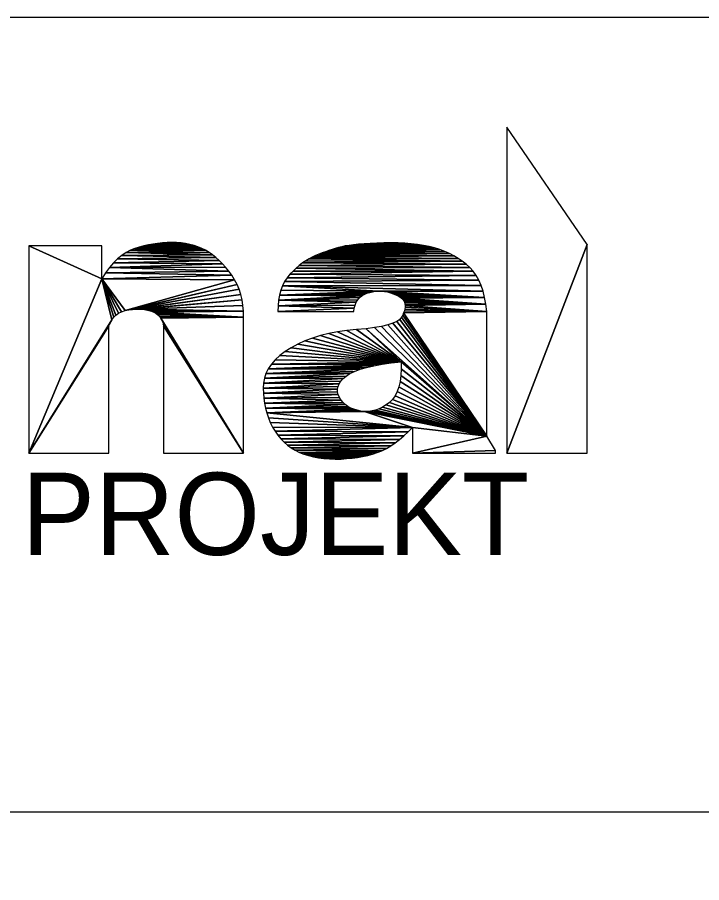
# Model space of a CAD drawing. Extents: x -1210 to -790, y -790 to -493.
# Drawn here: x -950.3 to -931.18, y -751.97 to -727.77 of the extents above; entities that cross this region are included whole.
import ezdxf

# ---------------------------------------------------------------- set-up
doc = ezdxf.new("R2010")
doc.units = 0
doc.layers.add('Vrstva 1', color=7, linetype='Continuous')

msp = doc.modelspace()

# ---------------------------------------------------------------- linework, layer by layer
at = {"layer": 'Vrstva 1'}
msp.add_line((-855, -750), (-970, -750), dxfattribs=at)
for points in [[(-970, -727.774), (-805, -727.774), (-805, -780), (-970, -780)], [(-936.62, -730.842), (-936.62, -739.962), (-934.38, -734.122)], [(-946.509, -734.114), (-946.638, -734.136), (-945.478, -734.124)], [(-946.379, -734.096), (-946.509, -734.114), (-945.597, -734.1)], [(-945.597, -734.1), (-946.509, -734.114), (-945.478, -734.124)], [(-946.247, -734.082), (-946.379, -734.096), (-945.721, -734.084)], [(-945.721, -734.084), (-946.379, -734.096), (-945.597, -734.1)], [(-946.115, -734.074), (-946.247, -734.082), (-945.721, -734.084)], [(-945.981, -734.072), (-946.115, -734.074), (-945.849, -734.074)], [(-945.849, -734.074), (-946.115, -734.074), (-945.721, -734.084)], [(-940.611, -734.104), (-940.766, -734.118), (-939.293, -734.106)], [(-939.293, -734.106), (-940.766, -734.118), (-939.119, -734.126)], [(-940.442, -734.094), (-940.611, -734.104), (-939.293, -734.106)], [(-940.258, -734.086), (-940.442, -734.094), (-939.474, -734.09)], [(-939.474, -734.09), (-940.442, -734.094), (-939.293, -734.106)], [(-940.059, -734.08), (-940.258, -734.086), (-939.661, -734.082)], [(-939.661, -734.082), (-940.258, -734.086), (-939.474, -734.09)], [(-939.857, -734.078), (-940.059, -734.08), (-939.661, -734.082)], [(-947.94, -735.082), (-947.94, -734.162), (-949.98, -734.162)], [(-949.98, -734.162), (-949.98, -739.962), (-947.94, -735.082)], [(-947.263, -734.348), (-947.382, -734.43), (-944.847, -734.414)], [(-947.142, -734.284), (-947.263, -734.348), (-945.044, -734.288)], [(-945.044, -734.288), (-947.263, -734.348), (-944.944, -734.346)], [(-944.944, -734.346), (-947.263, -734.348), (-944.847, -734.414)], [(-945.146, -734.236), (-947.142, -734.284), (-945.044, -734.288)], [(-947.018, -734.236), (-947.142, -734.284), (-945.146, -734.236)], [(-946.892, -734.198), (-947.018, -734.236), (-945.146, -734.236)], [(-946.766, -734.164), (-946.892, -734.198), (-945.252, -734.192)], [(-945.252, -734.192), (-946.892, -734.198), (-945.146, -734.236)], [(-946.638, -734.136), (-946.766, -734.164), (-945.363, -734.154)], [(-945.363, -734.154), (-946.766, -734.164), (-945.252, -734.192)], [(-945.478, -734.124), (-946.638, -734.136), (-945.363, -734.154)], [(-941.687, -734.328), (-941.779, -734.362), (-938.226, -734.376)], [(-941.595, -734.298), (-941.687, -734.328), (-938.358, -734.318)], [(-938.358, -734.318), (-941.687, -734.328), (-938.226, -734.376)], [(-941.505, -734.268), (-941.595, -734.298), (-938.358, -734.318)], [(-941.415, -734.24), (-941.505, -734.268), (-938.497, -734.266)], [(-938.497, -734.266), (-941.505, -734.268), (-938.358, -734.318)], [(-941.325, -734.214), (-941.415, -734.24), (-938.642, -734.222)], [(-938.642, -734.222), (-941.415, -734.24), (-938.497, -734.266)], [(-941.237, -734.19), (-941.325, -734.214), (-938.642, -734.222)], [(-941.141, -734.168), (-941.237, -734.19), (-938.794, -734.184)], [(-938.794, -734.184), (-941.237, -734.19), (-938.642, -734.222)], [(-941.03, -734.15), (-941.141, -734.168), (-938.953, -734.152)], [(-938.953, -734.152), (-941.141, -734.168), (-938.794, -734.184)], [(-940.905, -734.132), (-941.03, -734.15), (-938.953, -734.152)], [(-940.766, -734.118), (-940.905, -734.132), (-939.119, -734.126)], [(-939.119, -734.126), (-940.905, -734.132), (-938.953, -734.152)], [(-934.38, -734.122), (-936.62, -739.962), (-934.38, -739.962)], [(-947.498, -734.528), (-947.612, -734.642), (-944.659, -734.572)], [(-944.659, -734.572), (-947.612, -734.642), (-944.568, -734.664)], [(-947.382, -734.43), (-947.498, -734.528), (-944.752, -734.488)], [(-944.752, -734.488), (-947.498, -734.528), (-944.659, -734.572)], [(-944.847, -734.414), (-947.382, -734.43), (-944.752, -734.488)], [(-942.242, -734.58), (-942.332, -734.642), (-937.866, -734.592)], [(-937.866, -734.592), (-942.332, -734.642), (-937.759, -734.678)], [(-942.15, -734.524), (-942.242, -734.58), (-937.866, -734.592)], [(-942.058, -734.476), (-942.15, -734.524), (-937.98, -734.514)], [(-937.98, -734.514), (-942.15, -734.524), (-937.866, -734.592)], [(-941.965, -734.434), (-942.058, -734.476), (-938.1, -734.442)], [(-938.1, -734.442), (-942.058, -734.476), (-937.98, -734.514)], [(-941.871, -734.398), (-941.965, -734.434), (-938.1, -734.442)], [(-941.779, -734.362), (-941.871, -734.398), (-938.226, -734.376)], [(-938.226, -734.376), (-941.871, -734.398), (-938.1, -734.442)], [(-947.724, -734.772), (-947.833, -734.918), (-944.393, -734.872)], [(-947.612, -734.642), (-947.724, -734.772), (-944.568, -734.664)], [(-944.568, -734.664), (-947.724, -734.772), (-944.479, -734.764)], [(-944.479, -734.764), (-947.724, -734.772), (-944.393, -734.872)], [(-942.509, -734.788), (-942.596, -734.87), (-937.565, -734.874)], [(-942.421, -734.712), (-942.509, -734.788), (-937.658, -734.77)], [(-937.658, -734.77), (-942.509, -734.788), (-937.565, -734.874)], [(-942.332, -734.642), (-942.421, -734.712), (-937.759, -734.678)], [(-937.759, -734.678), (-942.421, -734.712), (-937.658, -734.77)], [(-947.94, -735.082), (-949.98, -739.962), (-947.662, -736.23)], [(-947.833, -734.918), (-947.94, -735.082), (-944.308, -734.988)], [(-944.308, -734.988), (-947.94, -735.082), (-944.229, -735.112)], [(-947.94, -735.082), (-947.291, -735.976), (-944.229, -735.112)], [(-947.94, -735.082), (-947.385, -736.006), (-947.291, -735.976)], [(-947.94, -735.082), (-947.469, -736.048), (-947.385, -736.006)], [(-947.94, -735.082), (-947.543, -736.098), (-947.469, -736.048)], [(-947.94, -735.082), (-947.607, -736.16), (-947.543, -736.098)], [(-947.94, -735.082), (-947.662, -736.23), (-947.607, -736.16)], [(-944.393, -734.872), (-947.833, -734.918), (-944.308, -734.988)], [(-942.763, -735.058), (-942.832, -735.164), (-937.407, -735.124)], [(-942.682, -734.96), (-942.763, -735.058), (-937.481, -734.992)], [(-937.481, -734.992), (-942.763, -735.058), (-937.407, -735.124)], [(-942.596, -734.87), (-942.682, -734.96), (-937.565, -734.874)], [(-937.565, -734.874), (-942.682, -734.96), (-937.481, -734.992)], [(-944.229, -735.112), (-947.291, -735.976), (-944.161, -735.242)], [(-944.161, -735.242), (-947.291, -735.976), (-947.187, -735.954)], [(-944.161, -735.242), (-947.187, -735.954), (-944.104, -735.378)], [(-942.89, -735.28), (-942.938, -735.406), (-940.209, -735.43)], [(-942.832, -735.164), (-942.89, -735.28), (-937.343, -735.27)], [(-937.343, -735.27), (-942.89, -735.28), (-937.288, -735.432)], [(-942.89, -735.28), (-940.209, -735.43), (-937.288, -735.432)], [(-937.407, -735.124), (-942.832, -735.164), (-937.343, -735.27)], [(-944.104, -735.378), (-947.187, -735.954), (-944.058, -735.522)], [(-944.058, -735.522), (-947.187, -735.954), (-947.081, -735.942)], [(-944.058, -735.522), (-947.081, -735.942), (-944.022, -735.672)], [(-942.975, -735.54), (-943.001, -735.686), (-940.678, -735.562)], [(-940.678, -735.562), (-943.001, -735.686), (-940.737, -735.612)], [(-942.938, -735.406), (-942.975, -735.54), (-940.209, -735.43)], [(-940.209, -735.43), (-942.975, -735.54), (-940.291, -735.434)], [(-940.291, -735.434), (-942.975, -735.54), (-940.373, -735.446)], [(-940.373, -735.446), (-942.975, -735.54), (-940.454, -735.464)], [(-940.454, -735.464), (-942.975, -735.54), (-940.535, -735.488)], [(-940.535, -735.488), (-942.975, -735.54), (-940.611, -735.52)], [(-940.611, -735.52), (-942.975, -735.54), (-940.678, -735.562)], [(-940.209, -735.43), (-940.127, -735.432), (-937.288, -735.432)], [(-940.127, -735.432), (-940.044, -735.44), (-937.288, -735.432)], [(-937.288, -735.432), (-940.044, -735.44), (-937.243, -735.608)], [(-940.044, -735.44), (-939.96, -735.454), (-937.243, -735.608)], [(-939.96, -735.454), (-939.876, -735.476), (-937.243, -735.608)], [(-939.876, -735.476), (-939.796, -735.502), (-937.243, -735.608)], [(-939.796, -735.502), (-939.724, -735.53), (-937.243, -735.608)], [(-939.724, -735.53), (-939.662, -735.56), (-937.243, -735.608)], [(-939.662, -735.56), (-939.608, -735.592), (-937.243, -735.608)], [(-944.022, -735.672), (-947.081, -735.942), (-946.98, -735.934)], [(-944.022, -735.672), (-946.98, -735.934), (-946.885, -735.934)], [(-944.022, -735.672), (-946.885, -735.934), (-943.998, -735.83)], [(-943.001, -735.686), (-943.016, -735.84), (-940.828, -735.74)], [(-940.828, -735.74), (-943.016, -735.84), (-940.861, -735.818)], [(-940.737, -735.612), (-943.001, -735.686), (-940.787, -735.672)], [(-940.787, -735.672), (-943.001, -735.686), (-940.828, -735.74)], [(-939.608, -735.592), (-939.563, -735.626), (-937.243, -735.608)], [(-937.243, -735.608), (-939.563, -735.626), (-937.207, -735.798)], [(-939.563, -735.626), (-939.526, -735.662), (-937.207, -735.798)], [(-939.526, -735.662), (-939.499, -735.7), (-937.207, -735.798)], [(-939.499, -735.7), (-939.48, -735.74), (-937.207, -735.798)], [(-939.48, -735.74), (-939.468, -735.784), (-937.207, -735.798)], [(-939.468, -735.784), (-939.463, -735.83), (-937.207, -735.798)], [(-937.207, -735.798), (-939.463, -735.83), (-937.18, -736.002)], [(-943.998, -735.83), (-946.885, -735.934), (-943.984, -735.992)], [(-946.885, -735.934), (-946.794, -735.938), (-943.984, -735.992)], [(-946.794, -735.938), (-946.709, -735.95), (-943.984, -735.992)], [(-946.709, -735.95), (-946.63, -735.968), (-943.984, -735.992)], [(-946.63, -735.968), (-946.555, -735.992), (-943.984, -735.992)], [(-946.555, -735.992), (-946.486, -736.022), (-943.984, -735.992)], [(-943.984, -735.992), (-946.486, -736.022), (-943.98, -736.162)], [(-946.486, -736.022), (-946.424, -736.056), (-943.98, -736.162)], [(-943.016, -735.84), (-943.02, -736.002), (-940.885, -735.906)], [(-940.885, -735.906), (-943.02, -736.002), (-940.9, -736.002)], [(-940.861, -735.818), (-943.016, -735.84), (-940.885, -735.906)], [(-939.506, -736.04), (-939.532, -736.1), (-937.18, -739.482)], [(-939.486, -735.984), (-939.506, -736.04), (-937.18, -736.002)], [(-937.18, -736.002), (-939.506, -736.04), (-937.18, -739.482)], [(-939.472, -735.93), (-939.486, -735.984), (-937.18, -736.002)], [(-939.464, -735.878), (-939.472, -735.93), (-937.18, -736.002)], [(-939.463, -735.83), (-939.464, -735.878), (-937.18, -736.002)], [(-947.662, -736.23), (-949.98, -739.962), (-947.706, -736.312)], [(-946.424, -736.056), (-946.37, -736.094), (-943.98, -736.162)], [(-946.37, -736.094), (-946.324, -736.136), (-943.98, -736.162)], [(-946.324, -736.136), (-946.287, -736.182), (-943.98, -736.162)], [(-943.98, -736.162), (-946.287, -736.182), (-943.98, -739.962)], [(-946.287, -736.182), (-946.258, -736.232), (-943.98, -739.962)], [(-946.258, -736.232), (-946.237, -736.284), (-943.98, -739.962)], [(-946.237, -736.284), (-946.225, -736.342), (-943.98, -739.962)], [(-939.696, -736.28), (-939.807, -736.33), (-937.18, -739.482)], [(-939.615, -736.224), (-939.696, -736.28), (-937.18, -739.482)], [(-939.564, -736.162), (-939.615, -736.224), (-937.18, -739.482)], [(-939.532, -736.1), (-939.564, -736.162), (-937.18, -739.482)], [(-947.706, -736.312), (-949.98, -739.962), (-947.74, -736.402)], [(-947.74, -736.402), (-949.98, -739.962), (-947.74, -739.962)], [(-946.225, -736.342), (-946.22, -736.402), (-943.98, -739.962)], [(-946.22, -736.402), (-946.22, -739.962), (-943.98, -739.962)], [(-941.091, -736.532), (-941.35, -736.568), (-939.576, -737.406)], [(-940.819, -736.504), (-941.091, -736.532), (-939.576, -737.406)], [(-940.556, -736.48), (-940.819, -736.504), (-939.576, -737.406)], [(-940.323, -736.45), (-940.556, -736.48), (-937.18, -739.482)], [(-940.556, -736.48), (-939.576, -737.406), (-937.18, -739.482)], [(-940.121, -736.416), (-940.323, -736.45), (-937.18, -739.482)], [(-939.949, -736.376), (-940.121, -736.416), (-937.18, -739.482)], [(-939.807, -736.33), (-939.949, -736.376), (-937.18, -739.482)], [(-942.055, -736.744), (-942.266, -736.824), (-939.576, -737.406)], [(-941.833, -736.674), (-942.055, -736.744), (-939.576, -737.406)], [(-941.598, -736.616), (-941.833, -736.674), (-939.576, -737.406)], [(-941.35, -736.568), (-941.598, -736.616), (-939.576, -737.406)], [(-942.65, -737.014), (-942.819, -737.122), (-939.576, -737.406)], [(-942.464, -736.914), (-942.65, -737.014), (-939.576, -737.406)], [(-942.266, -736.824), (-942.464, -736.914), (-939.576, -737.406)], [(-942.967, -737.234), (-943.095, -737.352), (-939.576, -737.406)], [(-942.819, -737.122), (-942.967, -737.234), (-939.576, -737.406)], [(-940.11, -737.474), (-943.287, -737.6), (-940.339, -737.516)], [(-943.201, -737.474), (-943.287, -737.6), (-940.11, -737.474)], [(-943.095, -737.352), (-943.201, -737.474), (-939.576, -737.406)], [(-939.576, -737.406), (-943.201, -737.474), (-939.855, -737.438)], [(-939.855, -737.438), (-943.201, -737.474), (-940.11, -737.474)], [(-939.576, -737.406), (-939.571, -737.606), (-937.18, -739.482)], [(-943.352, -737.73), (-943.396, -737.866), (-941.005, -737.736)], [(-941.005, -737.736), (-943.396, -737.866), (-941.108, -737.804)], [(-943.287, -737.6), (-943.352, -737.73), (-940.723, -737.616)], [(-940.723, -737.616), (-943.352, -737.73), (-940.876, -737.674)], [(-940.876, -737.674), (-943.352, -737.73), (-941.005, -737.736)], [(-940.339, -737.516), (-943.287, -737.6), (-940.544, -737.564)], [(-940.544, -737.564), (-943.287, -737.6), (-940.723, -737.616)], [(-939.571, -737.606), (-939.58, -737.788), (-937.18, -739.482)], [(-943.396, -737.866), (-943.419, -738.006), (-941.191, -737.876)], [(-941.191, -737.876), (-943.419, -738.006), (-941.257, -737.948)], [(-941.257, -737.948), (-943.419, -738.006), (-941.306, -738.022)], [(-941.108, -737.804), (-943.396, -737.866), (-941.191, -737.876)], [(-939.602, -737.954), (-939.636, -738.102), (-937.18, -739.482)], [(-939.58, -737.788), (-939.602, -737.954), (-937.18, -739.482)], [(-943.419, -738.006), (-943.427, -738.146), (-941.306, -738.022)], [(-941.306, -738.022), (-943.427, -738.146), (-941.338, -738.096)], [(-941.338, -738.096), (-943.427, -738.146), (-941.354, -738.172)], [(-943.427, -738.146), (-943.426, -738.286), (-941.354, -738.172)], [(-941.354, -738.172), (-943.426, -738.286), (-941.353, -738.248)], [(-939.636, -738.102), (-939.684, -738.236), (-937.18, -739.482)], [(-941.353, -738.248), (-943.426, -738.286), (-941.335, -738.324)], [(-943.426, -738.286), (-943.416, -738.426), (-941.335, -738.324)], [(-941.335, -738.324), (-943.416, -738.426), (-941.301, -738.402)], [(-941.301, -738.402), (-943.416, -738.426), (-941.254, -738.476)], [(-943.416, -738.426), (-943.397, -738.564), (-941.254, -738.476)], [(-939.818, -738.456), (-939.904, -738.54), (-937.18, -739.482)], [(-939.744, -738.354), (-939.818, -738.456), (-937.18, -739.482)], [(-939.684, -738.236), (-939.744, -738.354), (-937.18, -739.482)], [(-941.254, -738.476), (-943.397, -738.564), (-941.199, -738.544)], [(-941.199, -738.544), (-943.397, -738.564), (-941.136, -738.602)], [(-943.397, -738.564), (-943.369, -738.7), (-941.136, -738.602)], [(-941.136, -738.602), (-943.369, -738.7), (-941.065, -738.654)], [(-941.065, -738.654), (-943.369, -738.7), (-940.986, -738.698)], [(-940.986, -738.698), (-943.369, -738.7), (-940.9, -738.734)], [(-943.369, -738.7), (-943.332, -738.836), (-940.9, -738.734)], [(-940.093, -738.672), (-940.19, -738.718), (-937.18, -739.482)], [(-939.997, -738.612), (-940.093, -738.672), (-937.18, -739.482)], [(-939.904, -738.54), (-939.997, -738.612), (-937.18, -739.482)], [(-940.9, -738.734), (-943.332, -738.836), (-940.805, -738.762)], [(-940.805, -738.762), (-943.332, -738.836), (-940.702, -738.782)], [(-940.702, -738.782), (-943.332, -738.836), (-940.596, -738.792)], [(-940.596, -738.792), (-943.332, -738.836), (-939.26, -739.242)], [(-943.332, -738.836), (-943.286, -738.97), (-939.26, -739.242)], [(-940.596, -738.792), (-939.26, -739.242), (-937.18, -739.482)], [(-940.492, -738.792), (-940.596, -738.792), (-937.18, -739.482)], [(-940.389, -738.78), (-940.492, -738.792), (-937.18, -739.482)], [(-940.289, -738.754), (-940.389, -738.78), (-937.18, -739.482)], [(-940.19, -738.718), (-940.289, -738.754), (-937.18, -739.482)], [(-943.286, -738.97), (-943.231, -739.104), (-939.26, -739.242)], [(-943.231, -739.104), (-943.168, -739.232), (-939.26, -739.242)], [(-943.168, -739.232), (-943.098, -739.35), (-939.26, -739.242)], [(-939.26, -739.242), (-943.098, -739.35), (-939.378, -739.366)], [(-943.098, -739.35), (-943.021, -739.462), (-939.378, -739.366)], [(-939.378, -739.366), (-943.021, -739.462), (-939.496, -739.48)], [(-939.26, -739.242), (-939.26, -739.962), (-937.18, -739.482)], [(-943.021, -739.462), (-942.937, -739.562), (-939.496, -739.48)], [(-939.496, -739.48), (-942.937, -739.562), (-939.617, -739.582)], [(-942.937, -739.562), (-942.847, -739.656), (-939.617, -739.582)], [(-939.617, -739.582), (-942.847, -739.656), (-939.739, -739.676)], [(-942.847, -739.656), (-942.749, -739.74), (-939.739, -739.676)], [(-939.739, -739.676), (-942.749, -739.74), (-939.863, -739.758)], [(-937.18, -739.482), (-939.26, -739.962), (-936.94, -739.882)], [(-942.749, -739.74), (-942.645, -739.814), (-939.863, -739.758)], [(-939.863, -739.758), (-942.645, -739.814), (-939.988, -739.83)], [(-942.645, -739.814), (-942.533, -739.88), (-939.988, -739.83)], [(-939.988, -739.83), (-942.533, -739.88), (-940.115, -739.892)], [(-942.533, -739.88), (-942.415, -739.938), (-940.115, -739.892)], [(-940.115, -739.892), (-942.415, -739.938), (-940.244, -739.942)], [(-936.94, -739.882), (-939.26, -739.962), (-936.94, -739.962)], [(-942.415, -739.938), (-942.291, -739.988), (-940.244, -739.942)], [(-940.244, -739.942), (-942.291, -739.988), (-940.375, -739.986)], [(-940.375, -739.986), (-942.291, -739.988), (-940.511, -740.024)], [(-942.291, -739.988), (-942.161, -740.03), (-940.511, -740.024)], [(-940.511, -740.024), (-942.161, -740.03), (-940.652, -740.054)], [(-942.161, -740.03), (-942.024, -740.064), (-940.652, -740.054)], [(-940.652, -740.054), (-942.024, -740.064), (-940.796, -740.08)], [(-942.024, -740.064), (-941.882, -740.092), (-940.796, -740.08)], [(-940.796, -740.08), (-941.882, -740.092), (-940.945, -740.1)], [(-941.882, -740.092), (-941.733, -740.112), (-940.945, -740.1)], [(-940.945, -740.1), (-941.733, -740.112), (-941.098, -740.114)], [(-941.733, -740.112), (-941.579, -740.122), (-941.098, -740.114)], [(-941.098, -740.114), (-941.579, -740.122), (-941.256, -740.124)], [(-941.579, -740.122), (-941.418, -740.126), (-941.256, -740.124)]]:
    msp.add_lwpolyline(points, close=True, dxfattribs=at)

# ---------------------------------------------------------------- texts
msp.add_text('PROJEKT', height=2.299, dxfattribs=at).set_placement((-950.18, -742.806))

doc.saveas('drawing.dxf')
